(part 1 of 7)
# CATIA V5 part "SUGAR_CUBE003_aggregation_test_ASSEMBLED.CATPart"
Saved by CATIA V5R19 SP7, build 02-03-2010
Part number: sugar_cube_powercopy_revised
Bounding box of the stored display mesh (mm): x -8667.428 to 41555.613, y -8007.522 to 25321.48, z -5486.4 to 45720
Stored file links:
  C:\Users\kmdaub-admin\Desktop\zip\SUGAR_CUBE003_aggregation_test_ASSEMBLED.CATPart
  C:\Users\kmdaub-admin\Desktop\sugar_cubes\sugar_cube_lantern.CATPart
  C:\Users\kmdaub-admin\Desktop\sugar_cubes\sugar-cube-revised\SUGAR_CUBE003.CATPart
  C:\Users\kmdaub-admin\Desktop\sugar_cubes\sugar-cube-revised\sugar_cube003_revised_aggregation_test.xls
  C:\Users\kmdaub-admin\Desktop\zip\sugar_cube003_revised_aggregation_test2.xls
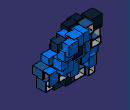
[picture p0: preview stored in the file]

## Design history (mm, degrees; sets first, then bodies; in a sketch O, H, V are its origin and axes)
Parameters
  thickness = 609.6 mm
  grid_spacing = 9144 mm
  overall_height = 39624 mm
  random_clamp = 0.5
AxisSystem1: origin (0, 0, 0), X (1, 0, 0), Y (0, 1, 0), Z (0, 0, 1)
Set1 "framework"
  Point1: (14630.4, 14630.4, 14630.4), in AxisSystem1
Set2 "framework_setup"
  Plane1: type Offset, RefPlane XY plane of AxisSystem1, Offset 39624 {= overall_height}
  Sketch1 on XY plane of AxisSystem1, origin (0, 0, 0), H (1, 0, 0), V (0, 1, 0)
    line L1 (83.4959, 142.8705) -> (139.9184, 442.4027)
    line L2 (383.0281, 86.448) -> (83.4959, 142.8705)
    construction line L3 (383.0281, 86.448) -> (139.9184, 442.4027)
    point P4 (261.4732, 264.4253)
    length L2 = 304.8
    length L1 = 304.8
    perpendicularity: L2 L1
    midpoint: P4 L3
  Sketch2 on Plane1, origin (0, 0, 39624), H (1, 0, 0), V (0, 1, 0)
    line L1 (171.3017, 531.5737) -> (279.4378, 246.6007)
    line L2 (279.4378, 246.6007) -> (564.4108, 354.7368)
    construction line L3 (171.3017, 531.5737) -> (564.4108, 354.7368)
    point P4 (367.8563, 443.1553)
    length L2 = 304.8
    length L1 = 304.8
    perpendicularity: L2 L1
    midpoint: P4 L3
  RectPattern1: of sketch element, direction 1 instances 5, spacing 9144 {= grid_spacing}, along sketch element reversed, direction 2 instances 5, spacing 9144 {= grid_spacing}, along sketch element
  RectPattern2: of sketch element, direction 1 instances 5, spacing 9144 {= grid_spacing}, along sketch element, direction 2 instances 5, spacing 9144 {= grid_spacing}, along sketch element reversed
Set3 "framework_powercopies"
  Set4 "framework_powercopy"
    Line1: type PtPt, FirstPoint vertex of RectPattern1, SecondPoint vertex of RectPattern2
    Point2: type OnCurve, Support Line1, Ratio 0.2
    Point3: type OnCurve, Support Line1, RefPoint Point2, Ratio 0.25 {= 1 / 4}
    Point4: type OnCurve, Support Line1, RefPoint Point2, Ratio 0.5 {= 2 / 4}
    Point5: type OnCurve, Support Line1, RefPoint Point2, Ratio 0.75 {= 3 / 4}
  Set5 "framework_powercopy"
    Line2: type PtPt, FirstPoint vertex of RectPattern1, SecondPoint vertex of RectPattern2
    Point6: type OnCurve, Support Line2, Ratio 0.2
    Point7: type OnCurve, Support Line2, RefPoint Point6, Ratio 0.25 {= 1 / 4}
    Point8: type OnCurve, Support Line2, RefPoint Point6, Ratio 0.5 {= 2 / 4}
    Point9: type OnCurve, Support Line2, RefPoint Point6, Ratio 0.75 {= 3 / 4}
  Set6 "framework_powercopy"
    Line3: type PtPt, FirstPoint vertex of RectPattern1, SecondPoint vertex of RectPattern2
    Point10: type OnCurve, Support Line3, Ratio 0.2
    Point11: type OnCurve, Support Line3, RefPoint Point10, Ratio 0.25 {= 1 / 4}
    Point12: type OnCurve, Support Line3, RefPoint Point10, Ratio 0.5 {= 2 / 4}
    Point13: type OnCurve, Support Line3, RefPoint Point10, Ratio 0.75 {= 3 / 4}
  Set7 "framework_powercopy"
    Line4: type PtPt, FirstPoint vertex of RectPattern1, SecondPoint vertex of RectPattern2
    Point14: type OnCurve, Support Line4, Ratio 0.2
    Point15: type OnCurve, Support Line4, RefPoint Point14, Ratio 0.25 {= 1 / 4}
    Point16: type OnCurve, Support Line4, RefPoint Point14, Ratio 0.5 {= 2 / 4}
    Point17: type OnCurve, Support Line4, RefPoint Point14, Ratio 0.75 {= 3 / 4}
  Set8 "framework_powercopy"
    Line5: type PtPt, FirstPoint vertex of RectPattern1, SecondPoint vertex of RectPattern2
    Point18: type OnCurve, Support Line5, Ratio 0.2
    Point19: type OnCurve, Support Line5, RefPoint Point18, Ratio 0.25 {= 1 / 4}
    Point20: type OnCurve, Support Line5, RefPoint Point18, Ratio 0.5 {= 2 / 4}
    Point21: type OnCurve, Support Line5, RefPoint Point18, Ratio 0.75 {= 3 / 4}
  Set9 "framework_powercopy"
    Line6: type PtPt, FirstPoint vertex of RectPattern1, SecondPoint vertex of RectPattern2
    Point22: type OnCurve, Support Line6, Ratio 0.2
    Point23: type OnCurve, Support Line6, RefPoint Point22, Ratio 0.25 {= 1 / 4}
    Point24: type OnCurve, Support Line6, RefPoint Point22, Ratio 0.5 {= 2 / 4}
    Point25: type OnCurve, Support Line6, RefPoint Point22, Ratio 0.75 {= 3 / 4}
  Set10 "framework_powercopy"
    Line7: type PtPt, FirstPoint vertex of RectPattern1, SecondPoint vertex of RectPattern2
    Point26: type OnCurve, Support Line7, Ratio 0.2
    Point27: type OnCurve, Support Line7, RefPoint Point26, Ratio 0.25 {= 1 / 4}
    Point28: type OnCurve, Support Line7, RefPoint Point26, Ratio 0.5 {= 2 / 4}
    Point29: type OnCurve, Support Line7, RefPoint Point26, Ratio 0.75 {= 3 / 4}
  Set11 "framework_powercopy"
    Line8: type PtPt, FirstPoint vertex of RectPattern1, SecondPoint vertex of RectPattern2
    Point30: type OnCurve, Support Line8, Ratio 0.2
    Point31: type OnCurve, Support Line8, RefPoint Point30, Ratio 0.25 {= 1 / 4}
    Point32: type OnCurve, Support Line8, RefPoint Point30, Ratio 0.5 {= 2 / 4}
    Point33: type OnCurve, Support Line8, RefPoint Point30, Ratio 0.75 {= 3 / 4}
  Set12 "framework_powercopy"
    Line9: type PtPt, FirstPoint vertex of RectPattern1, SecondPoint vertex of RectPattern2
    Point34: type OnCurve, Support Line9, Ratio 0.2
    Point35: type OnCurve, Support Line9, RefPoint Point34, Ratio 0.25 {= 1 / 4}
    Point36: type OnCurve, Support Line9, RefPoint Point34, Ratio 0.5 {= 2 / 4}
    Point37: type OnCurve, Support Line9, RefPoint Point34, Ratio 0.75 {= 3 / 4}
  Set13 "framework_powercopy"
    Line10: type PtPt, FirstPoint vertex of RectPattern1, SecondPoint vertex of RectPattern2
    Point38: type OnCurve, Support Line10, Ratio 0.2
    Point39: type OnCurve, Support Line10, RefPoint Point38, Ratio 0.25 {= 1 / 4}
    Point40: type OnCurve, Support Line10, RefPoint Point38, Ratio 0.5 {= 2 / 4}
    Point41: type OnCurve, Support Line10, RefPoint Point38, Ratio 0.75 {= 3 / 4}
  Set14 "framework_powercopy"
    Line11: type PtPt, FirstPoint vertex of RectPattern1, SecondPoint vertex of RectPattern2
    Point42: type OnCurve, Support Line11, Ratio 0.2
    Point43: type OnCurve, Support Line11, RefPoint Point42, Ratio 0.25 {= 1 / 4}
    Point44: type OnCurve, Support Line11, RefPoint Point42, Ratio 0.5 {= 2 / 4}
    Point45: type OnCurve, Support Line11, RefPoint Point42, Ratio 0.75 {= 3 / 4}
  Set15 "framework_powercopy"
    Line12: type PtPt, FirstPoint vertex of RectPattern1, SecondPoint vertex of RectPattern2
    Point46: type OnCurve, Support Line12, Ratio 0.2
    Point47: type OnCurve, Support Line12, RefPoint Point46, Ratio 0.25 {= 1 / 4}
    Point48: type OnCurve, Support Line12, RefPoint Point46, Ratio 0.5 {= 2 / 4}
    Point49: type OnCurve, Support Line12, RefPoint Point46, Ratio 0.75 {= 3 / 4}
  Set16 "framework_powercopy"
    Line13: type PtPt, FirstPoint vertex of RectPattern1, SecondPoint vertex of RectPattern2
    Point50: type OnCurve, Support Line13, Ratio 0.2
    Point51: type OnCurve, Support Line13, RefPoint Point50, Ratio 0.25 {= 1 / 4}
    Point52: type OnCurve, Support Line13, RefPoint Point50, Ratio 0.5 {= 2 / 4}
    Point53: type OnCurve, Support Line13, RefPoint Point50, Ratio 0.75 {= 3 / 4}
  Set17 "framework_powercopy"
    Line14: type PtPt, FirstPoint vertex of RectPattern1, SecondPoint vertex of RectPattern2
    Point54: type OnCurve, Support Line14, Ratio 0.2
    Point55: type OnCurve, Support Line14, RefPoint Point54, Ratio 0.25 {= 1 / 4}
    Point56: type OnCurve, Support Line14, RefPoint Point54, Ratio 0.5 {= 2 / 4}
    Point57: type OnCurve, Support Line14, RefPoint Point54, Ratio 0.75 {= 3 / 4}
  Set18 "framework_powercopy"
    Line15: type PtPt, FirstPoint vertex of RectPattern1, SecondPoint vertex of RectPattern2
    Point58: type OnCurve, Support Line15, Ratio 0.2
    Point59: type OnCurve, Support Line15, RefPoint Point58, Ratio 0.25 {= 1 / 4}
    Point60: type OnCurve, Support Line15, RefPoint Point58, Ratio 0.5 {= 2 / 4}
    Point61: type OnCurve, Support Line15, RefPoint Point58, Ratio 0.75 {= 3 / 4}
  Set19 "framework_powercopy"
    Line16: type PtPt, FirstPoint vertex of RectPattern1, SecondPoint vertex of RectPattern2
    Point62: type OnCurve, Support Line16, Ratio 0.2
    Point63: type OnCurve, Support Line16, RefPoint Point62, Ratio 0.25 {= 1 / 4}
    Point64: type OnCurve, Support Line16, RefPoint Point62, Ratio 0.5 {= 2 / 4}
    Point65: type OnCurve, Support Line16, RefPoint Point62, Ratio 0.75 {= 3 / 4}
  Set20 "framework_powercopy"
    Line17: type PtPt, FirstPoint vertex of RectPattern1, SecondPoint vertex of RectPattern2
    Point66: type OnCurve, Support Line17, Ratio 0.2
    Point67: type OnCurve, Support Line17, RefPoint Point66, Ratio 0.25 {= 1 / 4}
    Point68: type OnCurve, Support Line17, RefPoint Point66, Ratio 0.5 {= 2 / 4}
    Point69: type OnCurve, Support Line17, RefPoint Point66, Ratio 0.75 {= 3 / 4}
  Set21 "framework_powercopy"
    Line18: type PtPt, FirstPoint vertex of RectPattern1, SecondPoint vertex of RectPattern2
    Point70: type OnCurve, Support Line18, Ratio 0.2
    Point71: type OnCurve, Support Line18, RefPoint Point70, Ratio 0.25 {= 1 / 4}
    Point72: type OnCurve, Support Line18, RefPoint Point70, Ratio 0.5 {= 2 / 4}
    Point73: type OnCurve, Support Line18, RefPoint Point70, Ratio 0.75 {= 3 / 4}
  Set22 "framework_powercopy"
    Line19: type PtPt, FirstPoint vertex of RectPattern1, SecondPoint vertex of RectPattern2
    Point74: type OnCurve, Support Line19, Ratio 0.2
    Point75: type OnCurve, Support Line19, RefPoint Point74, Ratio 0.25 {= 1 / 4}
    Point76: type OnCurve, Support Line19, RefPoint Point74, Ratio 0.5 {= 2 / 4}
    Point77: type OnCurve, Support Line19, RefPoint Point74, Ratio 0.75 {= 3 / 4}
  Set23 "framework_powercopy"
    Line20: type PtPt, FirstPoint vertex of RectPattern1, SecondPoint vertex of RectPattern2
    Point78: type OnCurve, Support Line20, Ratio 0.2
    Point79: type OnCurve, Support Line20, RefPoint Point78, Ratio 0.25 {= 1 / 4}
    Point80: type OnCurve, Support Line20, RefPoint Point78, Ratio 0.5 {= 2 / 4}
    Point81: type OnCurve, Support Line20, RefPoint Point78, Ratio 0.75 {= 3 / 4}
  Set24 "framework_powercopy"
    Line21: type PtPt, FirstPoint vertex of RectPattern1, SecondPoint vertex of RectPattern2
    Point82: type OnCurve, Support Line21, Ratio 0.2
    Point83: type OnCurve, Support Line21, RefPoint Point82, Ratio 0.25 {= 1 / 4}
    Point84: type OnCurve, Support Line21, RefPoint Point82, Ratio 0.5 {= 2 / 4}
    Point85: type OnCurve, Support Line21, RefPoint Point82, Ratio 0.75 {= 3 / 4}
  Set25 "framework_powercopy"
    Line22: type PtPt, FirstPoint vertex of RectPattern1, SecondPoint vertex of RectPattern2
    Point86: type OnCurve, Support Line22, Ratio 0.2
    Point87: type OnCurve, Support Line22, RefPoint Point86, Ratio 0.25 {= 1 / 4}
    Point88: type OnCurve, Support Line22, RefPoint Point86, Ratio 0.5 {= 2 / 4}
    Point89: type OnCurve, Support Line22, RefPoint Point86, Ratio 0.75 {= 3 / 4}
  Set26 "framework_powercopy"
    Line23: type PtPt, FirstPoint vertex of RectPattern1, SecondPoint vertex of RectPattern2
    Point90: type OnCurve, Support Line23, Ratio 0.2
    Point91: type OnCurve, Support Line23, RefPoint Point90, Ratio 0.25 {= 1 / 4}
    Point92: type OnCurve, Support Line23, RefPoint Point90, Ratio 0.5 {= 2 / 4}
    Point93: type OnCurve, Support Line23, RefPoint Point90, Ratio 0.75 {= 3 / 4}
  Set27 "framework_powercopy"
    Line24: type PtPt, FirstPoint vertex of RectPattern1, SecondPoint vertex of RectPattern2
    Point94: type OnCurve, Support Line24, Ratio 0.2
    Point95: type OnCurve, Support Line24, RefPoint Point94, Ratio 0.25 {= 1 / 4}
    Point96: type OnCurve, Support Line24, RefPoint Point94, Ratio 0.5 {= 2 / 4}
    Point97: type OnCurve, Support Line24, RefPoint Point94, Ratio 0.75 {= 3 / 4}
  Line25: type PtPt, FirstPoint sketch element, SecondPoint sketch element
  Point98: type OnCurve, Support Line25, Ratio 0.2
  Point99: type OnCurve, Support Line25, RefPoint Point98, Ratio 0.25 {= 1 / 4}
  Point100: type OnCurve, Support Line25, RefPoint Point98, Ratio 0.5 {= 2 / 4}
  Point101: type OnCurve, Support Line25, RefPoint Point98, Ratio 0.75 {= 3 / 4}
Body1 "powercopy" (main body)
  Point102: (3048 {= Body1.X1}, 0, 0), relative to Point1, in AxisSystem1
  Point103: (-4572 {= Body1.X2}, 0, 0), relative to Point1, in AxisSystem1
  Point104: (0, 3657.6 {= Body1.Y1}, 0), relative to Point1, in AxisSystem1
  Point105: (0, -3657.6 {= Body1.Y2}, 0), relative to Point1, in AxisSystem1
  Plane2: type 3Points, Element1 Point1, Element2 Point104, Element3 Point102
  Plane3: type Offset, RefPlane Plane2, Offset 4267.2 {= Body1.Z1}, reversed
  Plane4: type Offset, RefPlane Plane2, Offset -3048 {= Body1.Z2}, reversed
  Sketch3 on Plane2, origin (0, 0, 14630.4), H (1, 0, 0), V (0, -1, 0)
    reference projected point E1 (17678.4, -14630.4) from Point102
    reference projected point E2 (14630.4, -10972.8) from Point105
    reference projected point E3 (10058.4, -14630.4) from Point103
    reference projected point E4 (14630.4, -18288) from Point104
    line L1 (17678.4, -18288) -> (10058.4, -18288)
    line L2 (10058.4, -18288) -> (10058.4, -10972.8)
    line L3 (10058.4, -10972.8) -> (17678.4, -10972.8)
    line L4 (17678.4, -10972.8) -> (17678.4, -18288)
    coincidence: E4 L1, E3 L2, E2 L3, L4 E1
    perpendicularity: L1 L2, L3 L2
    parallelism: L1 L3, L4 L2
    vertical: L2 V
  Pad1 "cube": profile Sketch3, direction (0, 0, -1), up to Plane3, opposite side up to Plane4
  Plane5: type Offset, RefPlane Plane3, Offset 609.6 {= thickness}
  Plane6: type Offset, RefPlane Plane4, Offset 609.6 {= thickness}, reversed
  Sketch4 on Plane2, origin (0, 0, 14630.4), H (1, 0, 0), V (0, -1, 0)
    reference projected point E1 (17678.4, -14630.4) from Point102
    reference projected point E2 (14630.4, -10972.8) from Point105
    reference projected point E3 (10058.4, -14630.4) from Point103
    reference projected point E4 (14630.4, -18288) from Point104
    construction line L1 (17678.4, -10972.8) -> (10058.4, -10972.8)
    construction line L2 (10058.4, -10972.8) -> (10058.4, -18288)
    construction line L3 (10058.4, -18288) -> (17678.4, -18288)
    construction line L4 (17678.4, -18288) -> (17678.4, -10972.8)
    line L5 (10668, -11582.4) -> (17068.8, -11582.4)
    line L6 (17068.8, -11582.4) -> (17068.8, -17678.4)
    line L7 (17068.8, -17678.4) -> (10668, -17678.4)
    line L8 (10668, -17678.4) -> (10668, -11582.4)
    distance L7 L3 = 609.6 {= thickness}
    distance L8 L2 = 609.6 {= thickness}
    distance L5 L1 = 609.6 {= thickness}
    distance L4 L6 = 609.6 {= thickness}
    horizontal: L1 H, L3 H, L5 H, L7 H
    vertical: L2 V, L4 V, L6 V, L8 V
    coincidence: L4 E1, E3 L2, L3 E4, E2 L1
  Pocket1 "internal_pocket": profile Sketch4, direction (0, 0, 1), up to Plane5, opposite side up to Plane6
  Plane7: type Offset, RefPlane face of Pad1 from Sketch3.L4, Offset 609.6 {= thickness}
  Sketch5 on face of Pad1 from Sketch3.L4, origin (17678.4, 0, 0), H (0, -1, 0), V (0, 0, 1)
    construction line L1 (-10972.8, 18897.6) -> (-18288, 18897.6)
    construction line L2 (-18288, 18897.6) -> (-18288, 11582.4)
    construction line L3 (-18288, 11582.4) -> (-10972.8, 11582.4)
    construction line L4 (-10972.8, 11582.4) -> (-10972.8, 18897.6)
    line L5 (-11582.4, 18288) -> (-17678.4, 18288)
    line L6 (-17678.4, 18288) -> (-17678.4, 12192)
    line L7 (-17678.4, 12192) -> (-11582.4, 12192)
    line L8 (-11582.4, 12192) -> (-11582.4, 18288)
    distance L5 L1 = 609.6 {= thickness}
    distance L6 L2 = 609.6 {= thickness}
    distance L3 L7 = 609.6 {= thickness}
    distance L4 L8 = 609.6 {= thickness}
    horizontal: L1 H, L3 H, L5 H, L7 H
    vertical: L2 V, L4 V, L6 V, L8 V
  Pocket2 "X1_pocket": profile Sketch5, direction (1, 0, 0), up to Plane7, deactivated
  Plane8: type Offset, RefPlane face of Pad1 from Sketch3.L1, Offset 609.6 {= thickness}
  Sketch6 on face of Pad1 from Sketch3.L1, origin (0, 18288, 0), H (1, 0, 0), V (0, 0, 1)
    construction line L1 (17678.4, 18897.6) -> (10058.4, 18897.6)
    construction line L2 (10058.4, 18897.6) -> (10058.4, 11582.4)
    construction line L3 (10058.4, 11582.4) -> (17678.4, 11582.4)
    construction line L4 (17678.4, 11582.4) -> (17678.4, 18897.6)
    line L5 (17068.8, 18288) -> (10668, 18288)
    line L6 (10668, 18288) -> (10668, 12192)
    line L7 (10668, 12192) -> (17068.8, 12192)
    line L8 (17068.8, 12192) -> (17068.8, 18288)
    distance L6 L2 = 609.6 {= thickness}
    distance L4 L8 = 609.6 {= thickness}
    distance L3 L7 = 609.6 {= thickness}
    distance L5 L1 = 609.6 {= thickness}
    horizontal: L1 H, L3 H, L5 H, L7 H
    vertical: L2 V, L4 V, L6 V, L8 V
  Pocket3 "Y1_pocket": profile Sketch6, direction (0, 1, 0), up to Plane8, deactivated
  Plane9: type Offset, RefPlane face of Pad1 from Sketch3.L2, Offset 609.6 {= thickness}
  Sketch7 on face of Pad1 from Sketch3.L2, origin (10058.4, 0, 0), H (0, -1, 0), V (0, 0, 1)
    construction line L1 (-18288, 18897.6) -> (-10972.8, 18897.6)
    construction line L2 (-10972.8, 18897.6) -> (-10972.8, 11582.4)
    construction line L3 (-10972.8, 11582.4) -> (-18288, 11582.4)
    construction line L4 (-18288, 11582.4) -> (-18288, 18897.6)
    line L5 (-17678.4, 18288) -> (-11582.4, 18288)
    line L6 (-11582.4, 18288) -> (-11582.4, 12192)
    line L7 (-11582.4, 12192) -> (-17678.4, 12192)
    line L8 (-17678.4, 12192) -> (-17678.4, 18288)
    distance L5 L1 = 609.6 {= thickness}
    distance L3 L7 = 609.6 {= thickness}
    distance L6 L2 = 609.6 {= thickness}
    distance L4 L8 = 609.6 {= thickness}
    horizontal: L1 H, L3 H, L5 H, L7 H
    vertical: L2 V, L4 V, L6 V, L8 V
  Pocket4 "X2_pocket": profile Sketch7, direction (1, 0, 0), up to Plane9, deactivated
  Plane10: type Offset, RefPlane face of Pad1 from Sketch3.L3, Offset 609.6 {= thickness}
  Sketch8 on face of Pad1 from Sketch3.L3, origin (0, 10972.8, 0), H (-1, 0, 0), V (0, 0, 1)
    construction line L1 (-10058.4, 18897.6) -> (-17678.4, 18897.6)
    construction line L2 (-17678.4, 18897.6) -> (-17678.4, 11582.4)
    construction line L3 (-17678.4, 11582.4) -> (-10058.4, 11582.4)
    construction line L4 (-10058.4, 11582.4) -> (-10058.4, 18897.6)
    line L5 (-10668, 18288) -> (-17068.8, 18288)
    line L6 (-17068.8, 18288) -> (-17068.8, 12192)
    line L7 (-17068.8, 12192) -> (-10668, 12192)
    line L8 (-10668, 12192) -> (-10668, 18288)
    distance L5 L1 = 609.6 {= thickness}
    distance L7 L3 = 609.6 {= thickness}
    distance L6 L2 = 609.6 {= thickness}
    distance L4 L8 = 609.6 {= thickness}
    horizontal: L1 H, L3 H, L5 H, L7 H
    vertical: L2 V, L4 V, L6 V, L8 V
  Pocket5 "Y2_pocket": profile Sketch8, direction (0, -1, 0), up to Plane10
  Translate1: ToTransfor Pocket5, Direction edge [XY plane of AxisSystem1 | ZX plane of AxisSystem1], Length 38.1
Body2 "sugar_cube003_Aa001"
  Line26: type PtDir, RefPoint vertex of RectPattern1, Direction edge [XY plane of AxisSystem1 | ZX plane of AxisSystem1], Start 0, End 4572 {= Body2.X1}
  Line27: type PtDir, RefPoint vertex of RectPattern1, Direction edge [XY plane of AxisSystem1 | ZX plane of AxisSystem1], Start 0, End 3048 {= Body2.X2}
  Line28: type PtDir, RefPoint vertex of RectPattern1, Direction edge [YZ plane of AxisSystem1 | XY plane of AxisSystem1], Start 0, End 5486.4 {= Body2.Y1}
  Line29: type PtDir, RefPoint vertex of RectPattern1, Direction edge [YZ plane of AxisSystem1 | XY plane of AxisSystem1], Start 0, End 3048 {= Body2.Y2}
  Line30: type PtDir, RefPoint vertex of RectPattern1, Direction edge [ZX plane of AxisSystem1 | YZ plane of AxisSystem1], Start 0, End 3962.4 {= Body2.Z1}
  Line31: type PtDir, RefPoint vertex of RectPattern1, Direction edge [ZX plane of AxisSystem1 | YZ plane of AxisSystem1], Start 0, End 4572 {= Body2.Z2}
  Plane11: type Normal, Curve Line26, RefPoint vertex of Line26
  Plane12: type Normal, Curve Line27, RefPoint vertex of Line27
  Plane13: type Normal, Curve Line28, RefPoint vertex of Line28
  Plane14: type Normal, Curve Line29, RefPoint vertex of Line29
  Plane15: type Normal, Curve Line30, RefPoint vertex of Line30
  Plane16: type Normal, Curve Line31, RefPoint vertex of Line31
  Plane17: type 3Points, Element1 vertex of RectPattern1, Element2 vertex of Line28, Element3 vertex of Line26
  Intersect1: ToIntersect1 Plane13, ToIntersect2 Plane12
  Intersect2: ToIntersect1 Plane11, ToIntersect2 Plane13
  Intersect3: ToIntersect1 Plane11, ToIntersect2 Plane14
  Intersect4: ToIntersect1 Plane14, ToIntersect2 Plane12
  MultiSel1
  LineCorner1: Elements ({intersect ToIntersect1 Plane17, ToIntersect2 Intersect3}; {intersect ToIntersect1 Plane17, ToIntersect2 Intersect4}; {intersect ToIntersect1 Plane17, ToIntersect2 Intersect1}; {intersect ToIntersect1 Plane17, ToIntersect2 Intersect2})
  Pad2: profile LineCorner1, up to Plane15, opposite side up to Plane16, deactivated
  Plane18: type Offset, RefPlane Plane14, Offset 609.6 {= thickness}
  Plane19: type Offset, RefPlane Plane13, Offset 609.6 {= thickness}, reversed
  Plane20: type Offset, RefPlane Plane11, Offset 609.6 {= thickness}, reversed
  Plane21: type Offset, RefPlane Plane12, Offset 609.6 {= thickness}
  Plane22: type Offset, RefPlane Plane16, Offset 609.6 {= thickness}
  Plane23: type Offset, RefPlane Plane15, Offset 609.6 {= thickness}, reversed
  Intersect5: ToIntersect1 Plane18, ToIntersect2 Plane11
  Intersect6: ToIntersect1 Plane19, ToIntersect2 Plane11
  Intersect7: ToIntersect1 Plane22, ToIntersect2 Plane11
  Intersect8: ToIntersect1 Plane23, ToIntersect2 Plane11
  Trim1: Trimmed (Intersect5; Intersect8)
  Trim2: Trimmed (Trim1; Intersect6)
  Trim3: Trimmed (Trim2; Intersect7)
  Pocket6: profile Trim3, up to Plane21, deactivated
  Pad3: profile LineCorner1, up to Plane15, opposite side up to Plane16, deactivated
  Intersect9: ToIntersect1 Plane19, ToIntersect2 Plane12
  Intersect10: ToIntersect1 Plane12, ToIntersect2 Plane18
  Intersect11: ToIntersect1 Plane22, ToIntersect2 Plane12
  Intersect12: ToIntersect1 Plane23, ToIntersect2 Plane12
  Trim4: Trimmed (Intersect12; Intersect9)
  Trim5: Trimmed (Trim4; Intersect11)
  Trim6: Trimmed (Trim5; Intersect10)
  Pocket7: profile Trim6, up to Plane20, deactivated
  Intersect13: ToIntersect1 Plane21, ToIntersect2 Plane14
  Intersect14: ToIntersect1 Plane22, ToIntersect2 Plane14
  Intersect15: ToIntersect1 Plane14, ToIntersect2 Plane20
  Intersect16: ToIntersect1 Plane23, ToIntersect2 Plane14
  Trim7: Trimmed (Intersect13; Intersect16)
  Trim8: Trimmed (Trim7; Intersect15)
  Trim9: Trimmed (Trim8; Intersect14)
  Pad4: profile LineCorner1, up to Plane15, opposite side up to Plane16, deactivated
  Pocket8: profile Trim9, up to Plane19, deactivated
  Intersect17: ToIntersect1 Plane20, ToIntersect2 Plane13
  Intersect18: ToIntersect1 Plane22, ToIntersect2 Plane13
  Intersect19: ToIntersect1 Plane21, ToIntersect2 Plane13
  Intersect20: ToIntersect1 Plane23, ToIntersect2 Plane13
  Trim10: Trimmed (Intersect17; Intersect20)
  Trim11: Trimmed (Trim10; Intersect19)
  Trim12: Trimmed (Trim11; Intersect18)
  Pad5: profile LineCorner1, up to Plane15, opposite side up to Plane16, deactivated
  Pocket9: profile Trim12, up to Plane18, deactivated
Body3 "sugar_cube003_Ab001"
  Line32: type PtDir, RefPoint vertex of RectPattern1, Direction edge [XY plane of AxisSystem1 | ZX plane of AxisSystem1], Start 0, End 5181.6 {= Body3.X1}
  Line33: type PtDir, RefPoint vertex of RectPattern1, Direction edge [XY plane of AxisSystem1 | ZX plane of AxisSystem1], Start 0, End 3352.8 {= Body3.X2}
  Line34: type PtDir, RefPoint vertex of RectPattern1, Direction edge [YZ plane of AxisSystem1 | XY plane of AxisSystem1], Start 0, End 5486.4 {= Body3.Y1}
  Line35: type PtDir, RefPoint vertex of RectPattern1, Direction edge [YZ plane of AxisSystem1 | XY plane of AxisSystem1], Start 0, End 4876.8 {= Body3.Y2}
  Line36: type PtDir, RefPoint vertex of RectPattern1, Direction edge [ZX plane of AxisSystem1 | YZ plane of AxisSystem1], Start 0, End 4572 {= Body3.Z1}
  Line37: type PtDir, RefPoint vertex of RectPattern1, Direction edge [ZX plane of AxisSystem1 | YZ plane of AxisSystem1], Start 0, End 3352.8 {= Body3.Z2}
  Plane24: type Normal, Curve Line32, RefPoint vertex of Line32
  Plane25: type Normal, Curve Line33, RefPoint vertex of Line33
  Plane26: type Normal, Curve Line34, RefPoint vertex of Line34
  Plane27: type Normal, Curve Line35, RefPoint vertex of Line35
  Plane28: type Normal, Curve Line36, RefPoint vertex of Line36
  Plane29: type Normal, Curve Line37, RefPoint vertex of Line37
  Plane30: type 3Points, Element1 vertex of RectPattern1, Element2 vertex of Line34, Element3 vertex of Line32
  Intersect21: ToIntersect1 Plane26, ToIntersect2 Plane25
  Intersect22: ToIntersect1 Plane24, ToIntersect2 Plane26
  Intersect23: ToIntersect1 Plane24, ToIntersect2 Plane27
  Intersect24: ToIntersect1 Plane27, ToIntersect2 Plane25
  MultiSel2
  LineCorner2: Elements ({intersect ToIntersect1 Plane30, ToIntersect2 Intersect23}; {intersect ToIntersect1 Plane30, ToIntersect2 Intersect24}; {intersect ToIntersect1 Plane30, ToIntersect2 Intersect21}; {intersect ToIntersect1 Plane30, ToIntersect2 Intersect22})
  Pad6: profile LineCorner2, up to Plane28, opposite side up to Plane29, deactivated
  Plane31: type Offset, RefPlane Plane27, Offset 609.6 {= thickness}
  Plane32: type Offset, RefPlane Plane26, Offset 609.6 {= thickness}, reversed
  Plane33: type Offset, RefPlane Plane24, Offset 609.6 {= thickness}, reversed
  Plane34: type Offset, RefPlane Plane25, Offset 609.6 {= thickness}
  Plane35: type Offset, RefPlane Plane29, Offset 609.6 {= thickness}
  Plane36: type Offset, RefPlane Plane28, Offset 609.6 {= thickness}, reversed
  Intersect25: ToIntersect1 Plane31, ToIntersect2 Plane24
  Intersect26: ToIntersect1 Plane32, ToIntersect2 Plane24
  Intersect27: ToIntersect1 Plane35, ToIntersect2 Plane24
  Intersect28: ToIntersect1 Plane36, ToIntersect2 Plane24
  Trim13: Trimmed (Intersect25; Intersect28)
  Trim14: Trimmed (Trim13; Intersect26)
  Trim15: Trimmed (Trim14; Intersect27)
  Pocket10: profile Trim15, up to Plane34, deactivated
  Pad7: profile LineCorner2, up to Plane28, opposite side up to Plane29, deactivated
  Intersect29: ToIntersect1 Plane32, ToIntersect2 Plane25
  Intersect30: ToIntersect1 Plane25, ToIntersect2 Plane31
  Intersect31: ToIntersect1 Plane35, ToIntersect2 Plane25
  Intersect32: ToIntersect1 Plane36, ToIntersect2 Plane25
  Trim16: Trimmed (Intersect32; Intersect29)
  Trim17: Trimmed (Trim16; Intersect31)
  Trim18: Trimmed (Trim17; Intersect30)
  Pocket11: profile Trim18, up to Plane33, deactivated
  Intersect33: ToIntersect1 Plane34, ToIntersect2 Plane27
  Intersect34: ToIntersect1 Plane35, ToIntersect2 Plane27
  Intersect35: ToIntersect1 Plane27, ToIntersect2 Plane33
  Intersect36: ToIntersect1 Plane36, ToIntersect2 Plane27
  Trim19: Trimmed (Intersect33; Intersect36)
  Trim20: Trimmed (Trim19; Intersect35)
  Trim21: Trimmed (Trim20; Intersect34)
  Pad8: profile LineCorner2, up to Plane28, opposite side up to Plane29, deactivated
  Pocket12: profile Trim21, up to Plane32, deactivated
  Intersect37: ToIntersect1 Plane33, ToIntersect2 Plane26
  Intersect38: ToIntersect1 Plane35, ToIntersect2 Plane26
  Intersect39: ToIntersect1 Plane34, ToIntersect2 Plane26
  Intersect40: ToIntersect1 Plane36, ToIntersect2 Plane26
  Trim22: Trimmed (Intersect37; Intersect40)
  Trim23: Trimmed (Trim22; Intersect39)
  Trim24: Trimmed (Trim23; Intersect38)
  Pad9: profile LineCorner2, up to Plane28, opposite side up to Plane29, deactivated
  Pocket13: profile Trim24, up to Plane31, deactivated
Body4 "sugar_cube003_Ac001"
  Line38: type PtDir, RefPoint vertex of RectPattern1, Direction edge [XY plane of AxisSystem1 | ZX plane of AxisSystem1], Start 0, End 4876.8 {= Body4.X1}
  Line39: type PtDir, RefPoint vertex of RectPattern1, Direction edge [XY plane of AxisSystem1 | ZX plane of AxisSystem1], Start 0, End 5486.4 {= Body4.X2}
  Line40: type PtDir, RefPoint vertex of RectPattern1, Direction edge [YZ plane of AxisSystem1 | XY plane of AxisSystem1], Start 0, End 6096 {= Body4.Y1}
  Line41: type PtDir, RefPoint vertex of RectPattern1, Direction edge [YZ plane of AxisSystem1 | XY plane of AxisSystem1], Start 0, End 5486.4 {= Body4.Y2}
  Line42: type PtDir, RefPoint vertex of RectPattern1, Direction edge [ZX plane of AxisSystem1 | YZ plane of AxisSystem1], Start 0, End 3352.8 {= Body4.Z1}
  Line43: type PtDir, RefPoint vertex of RectPattern1, Direction edge [ZX plane of AxisSystem1 | YZ plane of AxisSystem1], Start 0, End 4572 {= Body4.Z2}
  Plane37: type Normal, Curve Line38, RefPoint vertex of Line38
  Plane38: type Normal, Curve Line39, RefPoint vertex of Line39
  Plane39: type Normal, Curve Line40, RefPoint vertex of Line40
  Plane40: type Normal, Curve Line41, RefPoint vertex of Line41
  Plane41: type Normal, Curve Line42, RefPoint vertex of Line42
  Plane42: type Normal, Curve Line43, RefPoint vertex of Line43
  Plane43: type 3Points, Element1 vertex of RectPattern1, Element2 vertex of Line40, Element3 vertex of Line38
  Intersect41: ToIntersect1 Plane39, ToIntersect2 Plane38
  Intersect42: ToIntersect1 Plane37, ToIntersect2 Plane39
  Intersect43: ToIntersect1 Plane37, ToIntersect2 Plane40
  Intersect44: ToIntersect1 Plane40, ToIntersect2 Plane38
  MultiSel3
  LineCorner3: Elements ({intersect ToIntersect1 Plane43, ToIntersect2 Intersect43}; {intersect ToIntersect1 Plane43, ToIntersect2 Intersect44}; {intersect ToIntersect1 Plane43, ToIntersect2 Intersect41}; {intersect ToIntersect1 Plane43, ToIntersect2 Intersect42})
  Pad10: profile LineCorner3, up to Plane41, opposite side up to Plane42, deactivated
  Plane44: type Offset, RefPlane Plane40, Offset 609.6 {= thickness}
  Plane45: type Offset, RefPlane Plane39, Offset 609.6 {= thickness}, reversed
  Plane46: type Offset, RefPlane Plane37, Offset 609.6 {= thickness}, reversed
  Plane47: type Offset, RefPlane Plane38, Offset 609.6 {= thickness}
  Plane48: type Offset, RefPlane Plane42, Offset 609.6 {= thickness}
  Plane49: type Offset, RefPlane Plane41, Offset 609.6 {= thickness}, reversed
  Intersect45: ToIntersect1 Plane44, ToIntersect2 Plane37
  Intersect46: ToIntersect1 Plane45, ToIntersect2 Plane37
  Intersect47: ToIntersect1 Plane48, ToIntersect2 Plane37
  Intersect48: ToIntersect1 Plane49, ToIntersect2 Plane37
  Trim25: Trimmed (Intersect45; Intersect48)
  Trim26: Trimmed (Trim25; Intersect46)
  Trim27: Trimmed (Trim26; Intersect47)
  Pocket14: profile Trim27, up to Plane47, deactivated
  Pad11: profile LineCorner3, up to Plane41, opposite side up to Plane42, deactivated
  Intersect49: ToIntersect1 Plane45, ToIntersect2 Plane38
  Intersect50: ToIntersect1 Plane38, ToIntersect2 Plane44
  Intersect51: ToIntersect1 Plane48, ToIntersect2 Plane38
  Intersect52: ToIntersect1 Plane49, ToIntersect2 Plane38
  Trim28: Trimmed (Intersect52; Intersect49)
  Trim29: Trimmed (Trim28; Intersect51)
  Trim30: Trimmed (Trim29; Intersect50)
  Pocket15: profile Trim30, up to Plane46, deactivated
  Intersect53: ToIntersect1 Plane47, ToIntersect2 Plane40
  Intersect54: ToIntersect1 Plane48, ToIntersect2 Plane40
  Intersect55: ToIntersect1 Plane40, ToIntersect2 Plane46
  Intersect56: ToIntersect1 Plane49, ToIntersect2 Plane40
  Trim31: Trimmed (Intersect53; Intersect56)
  Trim32: Trimmed (Trim31; Intersect55)
  Trim33: Trimmed (Trim32; Intersect54)
  Pad12: profile LineCorner3, up to Plane41, opposite side up to Plane42, deactivated
  Pocket16: profile Trim33, up to Plane45, deactivated
  Intersect57: ToIntersect1 Plane46, ToIntersect2 Plane39
  Intersect58: ToIntersect1 Plane48, ToIntersect2 Plane39
  Intersect59: ToIntersect1 Plane47, ToIntersect2 Plane39
  Intersect60: ToIntersect1 Plane49, ToIntersect2 Plane39
  Trim34: Trimmed (Intersect57; Intersect60)
  Trim35: Trimmed (Trim34; Intersect59)
  Trim36: Trimmed (Trim35; Intersect58)
  Pad13: profile LineCorner3, up to Plane41, opposite side up to Plane42, deactivated
  Pocket17: profile Trim36, up to Plane44, deactivated
Body5 "sugar_cube003_Ad001"
  Line44: type PtDir, RefPoint vertex of RectPattern1, Direction edge [XY plane of AxisSystem1 | ZX plane of AxisSystem1], Start 0, End 3657.6 {= Body5.X1}
  Line45: type PtDir, RefPoint vertex of RectPattern1, Direction edge [XY plane of AxisSystem1 | ZX plane of AxisSystem1], Start 0, End 3962.4 {= Body5.X2}
  Line46: type PtDir, RefPoint vertex of RectPattern1, Direction edge [YZ plane of AxisSystem1 | XY plane of AxisSystem1], Start 0, End 6096 {= Body5.Y1}
  Line47: type PtDir, RefPoint vertex of RectPattern1, Direction edge [YZ plane of AxisSystem1 | XY plane of AxisSystem1], Start 0, End 4267.2 {= Body5.Y2}
  Line48: type PtDir, RefPoint vertex of RectPattern1, Direction edge [ZX plane of AxisSystem1 | YZ plane of AxisSystem1], Start 0, End 5791.2 {= Body5.Z1}
  Line49: type PtDir, RefPoint vertex of RectPattern1, Direction edge [ZX plane of AxisSystem1 | YZ plane of AxisSystem1], Start 0, End 3352.8 {= Body5.Z2}
  Plane50: type Normal, Curve Line44, RefPoint vertex of Line44
  Plane51: type Normal, Curve Line45, RefPoint vertex of Line45
  Plane52: type Normal, Curve Line46, RefPoint vertex of Line46
  Plane53: type Normal, Curve Line47, RefPoint vertex of Line47
  Plane54: type Normal, Curve Line48, RefPoint vertex of Line48
  Plane55: type Normal, Curve Line49, RefPoint vertex of Line49
  Plane56: type 3Points, Element1 vertex of RectPattern1, Element2 vertex of Line46, Element3 vertex of Line44
  Intersect61: ToIntersect1 Plane52, ToIntersect2 Plane51
  Intersect62: ToIntersect1 Plane50, ToIntersect2 Plane52
  Intersect63: ToIntersect1 Plane50, ToIntersect2 Plane53
  Intersect64: ToIntersect1 Plane53, ToIntersect2 Plane51
  MultiSel4
  LineCorner4: Elements ({intersect ToIntersect1 Plane56, ToIntersect2 Intersect63}; {intersect ToIntersect1 Plane56, ToIntersect2 Intersect64}; {intersect ToIntersect1 Plane56, ToIntersect2 Intersect61}; {intersect ToIntersect1 Plane56, ToIntersect2 Intersect62})
  Pad14: profile LineCorner4, up to Plane54, opposite side up to Plane55
  Plane57: type Offset, RefPlane Plane53, Offset 609.6 {= thickness}
  Plane58: type Offset, RefPlane Plane52, Offset 609.6 {= thickness}, reversed
  Plane59: type Offset, RefPlane Plane50, Offset 609.6 {= thickness}, reversed
  Plane60: type Offset, RefPlane Plane51, Offset 609.6 {= thickness}
  Plane61: type Offset, RefPlane Plane55, Offset 609.6 {= thickness}
  Plane62: type Offset, RefPlane Plane54, Offset 609.6 {= thickness}, reversed
  Intersect65: ToIntersect1 Plane57, ToIntersect2 Plane50
  Intersect66: ToIntersect1 Plane58, ToIntersect2 Plane50
  Intersect67: ToIntersect1 Plane61, ToIntersect2 Plane50
  Intersect68: ToIntersect1 Plane62, ToIntersect2 Plane50
  Trim37: Trimmed (Intersect65; Intersect68)
  Trim38: Trimmed (Trim37; Intersect66)
  Trim39: Trimmed (Trim38; Intersect67)
  Pocket18: profile Trim39, up to Plane60, deactivated
  Pad15: profile LineCorner4, up to Plane54, opposite side up to Plane55, deactivated
  Intersect69: ToIntersect1 Plane58, ToIntersect2 Plane51
  Intersect70: ToIntersect1 Plane51, ToIntersect2 Plane57
  Intersect71: ToIntersect1 Plane61, ToIntersect2 Plane51
  Intersect72: ToIntersect1 Plane62, ToIntersect2 Plane51
  Trim40: Trimmed (Intersect72; Intersect69)
  Trim41: Trimmed (Trim40; Intersect71)
  Trim42: Trimmed (Trim41; Intersect70)
  Pocket19: profile Trim42, up to Plane59, deactivated
  Intersect73: ToIntersect1 Plane60, ToIntersect2 Plane53
  Intersect74: ToIntersect1 Plane61, ToIntersect2 Plane53
  Intersect75: ToIntersect1 Plane53, ToIntersect2 Plane59
  Intersect76: ToIntersect1 Plane62, ToIntersect2 Plane53
  Trim43: Trimmed (Intersect73; Intersect76)
  Trim44: Trimmed (Trim43; Intersect75)
  Trim45: Trimmed (Trim44; Intersect74)
  Pad16: profile LineCorner4, up to Plane54, opposite side up to Plane55, deactivated
  Pocket20: profile Trim45, up to Plane58, deactivated
  Intersect77: ToIntersect1 Plane59, ToIntersect2 Plane52
  Intersect78: ToIntersect1 Plane61, ToIntersect2 Plane52
  Intersect79: ToIntersect1 Plane60, ToIntersect2 Plane52
  Intersect80: ToIntersect1 Plane62, ToIntersect2 Plane52
  Trim46: Trimmed (Intersect77; Intersect80)
  Trim47: Trimmed (Trim46; Intersect79)
  Trim48: Trimmed (Trim47; Intersect78)
  Pad17: profile LineCorner4, up to Plane54, opposite side up to Plane55
  Pocket21: profile Trim48, up to Plane57
Body6 "sugar_cube003_Ae001"
  Line50: type PtDir, RefPoint sketch element, Direction edge [XY plane of AxisSystem1 | ZX plane of AxisSystem1], Start 0, End 6096 {= Body6.X1}
  Line51: type PtDir, RefPoint sketch element, Direction edge [XY plane of AxisSystem1 | ZX plane of AxisSystem1], Start 0, End 3657.6 {= Body6.X2}
  Line52: type PtDir, RefPoint sketch element, Direction edge [YZ plane of AxisSystem1 | XY plane of AxisSystem1], Start 0, End 4267.2 {= Body6.Y1}
  Line53: type PtDir, RefPoint sketch element, Direction edge [YZ plane of AxisSystem1 | XY plane of AxisSystem1], Start 0, End 4876.8 {= Body6.Y2}
  Line54: type PtDir, RefPoint sketch element, Direction edge [ZX plane of AxisSystem1 | YZ plane of AxisSystem1], Start 0, End 4267.2 {= Body6.Z1}
  Line55: type PtDir, RefPoint sketch element, Direction edge [ZX plane of AxisSystem1 | YZ plane of AxisSystem1], Start 0, End 3352.8 {= Body6.Z2}
  Plane63: type Normal, Curve Line50, RefPoint vertex of Line50
  Plane64: type Normal, Curve Line51, RefPoint vertex of Line51
  Plane65: type Normal, Curve Line52, RefPoint vertex of Line52
  Plane66: type Normal, Curve Line53, RefPoint vertex of Line53
  Plane67: type Normal, Curve Line54, RefPoint vertex of Line54
  Plane68: type Normal, Curve Line55, RefPoint vertex of Line55
  Plane69: type 3Points, Element1 sketch element, Element2 vertex of Line52, Element3 vertex of Line50
  Intersect81: ToIntersect1 Plane65, ToIntersect2 Plane64
  Intersect82: ToIntersect1 Plane63, ToIntersect2 Plane65
  Intersect83: ToIntersect1 Plane63, ToIntersect2 Plane66
  Intersect84: ToIntersect1 Plane66, ToIntersect2 Plane64
  MultiSel5
  LineCorner5: Elements ({intersect ToIntersect1 Plane69, ToIntersect2 Intersect83}; {intersect ToIntersect1 Plane69, ToIntersect2 Intersect84}; {intersect ToIntersect1 Plane69, ToIntersect2 Intersect81}; {intersect ToIntersect1 Plane69, ToIntersect2 Intersect82})
  Pad18: profile LineCorner5, up to Plane67, opposite side up to Plane68, deactivated
  Plane70: type Offset, RefPlane Plane66, Offset 609.6 {= thickness}
  Plane71: type Offset, RefPlane Plane65, Offset 609.6 {= thickness}, reversed
  Plane72: type Offset, RefPlane Plane63, Offset 609.6 {= thickness}, reversed
  Plane73: type Offset, RefPlane Plane64, Offset 609.6 {= thickness}
  Plane74: type Offset, RefPlane Plane68, Offset 609.6 {= thickness}
  Plane75: type Offset, RefPlane Plane67, Offset 609.6 {= thickness}, reversed
  Intersect85: ToIntersect1 Plane70, ToIntersect2 Plane63
  Intersect86: ToIntersect1 Plane71, ToIntersect2 Plane63
  Intersect87: ToIntersect1 Plane74, ToIntersect2 Plane63
  Intersect88: ToIntersect1 Plane75, ToIntersect2 Plane63
  Trim49: Trimmed (Intersect85; Intersect88)
  Trim50: Trimmed (Trim49; Intersect86)
  Trim51: Trimmed (Trim50; Intersect87)
  Pocket22: profile Trim51, up to Plane73, deactivated
  Pad19: profile LineCorner5, up to Plane67, opposite side up to Plane68, deactivated
  Intersect89: ToIntersect1 Plane71, ToIntersect2 Plane64
  Intersect90: ToIntersect1 Plane64, ToIntersect2 Plane70
  Intersect91: ToIntersect1 Plane74, ToIntersect2 Plane64
  Intersect92: ToIntersect1 Plane75, ToIntersect2 Plane64
  Trim52: Trimmed (Intersect92; Intersect89)
  Trim53: Trimmed (Trim52; Intersect91)
  Trim54: Trimmed (Trim53; Intersect90)
  Pocket23: profile Trim54, up to Plane72, deactivated
  Intersect93: ToIntersect1 Plane73, ToIntersect2 Plane66
  Intersect94: ToIntersect1 Plane74, ToIntersect2 Plane66
  Intersect95: ToIntersect1 Plane66, ToIntersect2 Plane72
  Intersect96: ToIntersect1 Plane75, ToIntersect2 Plane66
  Trim55: Trimmed (Intersect93; Intersect96)
  Trim56: Trimmed (Trim55; Intersect95)
  Trim57: Trimmed (Trim56; Intersect94)
  Pad20: profile LineCorner5, up to Plane67, opposite side up to Plane68, deactivated
  Pocket24: profile Trim57, up to Plane71, deactivated
  Intersect97: ToIntersect1 Plane72, ToIntersect2 Plane65
  Intersect98: ToIntersect1 Plane74, ToIntersect2 Plane65
  Intersect99: ToIntersect1 Plane73, ToIntersect2 Plane65
  Intersect100: ToIntersect1 Plane75, ToIntersect2 Plane65
  Trim58: Trimmed (Intersect97; Intersect100)
  Trim59: Trimmed (Trim58; Intersect99)
  Trim60: Trimmed (Trim59; Intersect98)
  Pad21: profile LineCorner5, up to Plane67, opposite side up to Plane68, deactivated
  Pocket25: profile Trim60, up to Plane70, deactivated
Body7 "sugar_cube003_Aa002"
  Line56: type PtDir, RefPoint Point14, Direction edge [XY plane of AxisSystem1 | ZX plane of AxisSystem1], Start 0, End 4267.2 {= Body7.X1}
  Line57: type PtDir, RefPoint Point14, Direction edge [XY plane of AxisSystem1 | ZX plane of AxisSystem1], Start 0, End 3962.4 {= Body7.X2}
  Line58: type PtDir, RefPoint Point14, Direction edge [YZ plane of AxisSystem1 | XY plane of AxisSystem1], Start 0, End 6096 {= Body7.Y1}
  Line59: type PtDir, RefPoint Point14, Direction edge [YZ plane of AxisSystem1 | XY plane of AxisSystem1], Start 0, End 5486.4 {= Body7.Y2}
  Line60: type PtDir, RefPoint Point14, Direction edge [ZX plane of AxisSystem1 | YZ plane of AxisSystem1], Start 0, End 4267.2 {= Body7.Z1}
  Line61: type PtDir, RefPoint Point14, Direction edge [ZX plane of AxisSystem1 | YZ plane of AxisSystem1], Start 0, End 3352.8 {= Body7.Z2}
  Plane76: type Normal, Curve Line56, RefPoint vertex of Line56
  Plane77: type Normal, Curve Line57, RefPoint vertex of Line57
  Plane78: type Normal, Curve Line58, RefPoint vertex of Line58
  Plane79: type Normal, Curve Line59, RefPoint vertex of Line59
  Plane80: type Normal, Curve Line60, RefPoint vertex of Line60
  Plane81: type Normal, Curve Line61, RefPoint vertex of Line61
  Plane82: type 3Points, Element1 Point14, Element2 vertex of Line58, Element3 vertex of Line56
  Intersect101: ToIntersect1 Plane78, ToIntersect2 Plane77
  Intersect102: ToIntersect1 Plane76, ToIntersect2 Plane78
  Intersect103: ToIntersect1 Plane76, ToIntersect2 Plane79
  Intersect104: ToIntersect1 Plane79, ToIntersect2 Plane77
  MultiSel6
  LineCorner6: Elements ({intersect ToIntersect1 Plane82, ToIntersect2 Intersect103}; {intersect ToIntersect1 Plane82, ToIntersect2 Intersect104}; {intersect ToIntersect1 Plane82, ToIntersect2 Intersect101}; {intersect ToIntersect1 Plane82, ToIntersect2 Intersect102})
  Pad22: profile LineCorner6, up to Plane80, opposite side up to Plane81
  Plane83: type Offset, RefPlane Plane79, Offset 609.6 {= thickness}
  Plane84: type Offset, RefPlane Plane78, Offset 609.6 {= thickness}, reversed
  Plane85: type Offset, RefPlane Plane76, Offset 609.6 {= thickness}, reversed
  Plane86: type Offset, RefPlane Plane77, Offset 609.6 {= thickness}
  Plane87: type Offset, RefPlane Plane81, Offset 609.6 {= thickness}
  Plane88: type Offset, RefPlane Plane80, Offset 609.6 {= thickness}, reversed
  Intersect105: ToIntersect1 Plane83, ToIntersect2 Plane76
  Intersect106: ToIntersect1 Plane84, ToIntersect2 Plane76
  Intersect107: ToIntersect1 Plane87, ToIntersect2 Plane76
  Intersect108: ToIntersect1 Plane88, ToIntersect2 Plane76
  Trim61: Trimmed (Intersect105; Intersect108)
  Trim62: Trimmed (Trim61; Intersect106)
  Trim63: Trimmed (Trim62; Intersect107)
  Pocket26: profile Trim63, up to Plane86, deactivated
  Pad23: profile LineCorner6, up to Plane80, opposite side up to Plane81, deactivated
  Intersect109: ToIntersect1 Plane84, ToIntersect2 Plane77
  Intersect110: ToIntersect1 Plane77, ToIntersect2 Plane83
  Intersect111: ToIntersect1 Plane87, ToIntersect2 Plane77
  Intersect112: ToIntersect1 Plane88, ToIntersect2 Plane77
  Trim64: Trimmed (Intersect112; Intersect109)
  Trim65: Trimmed (Trim64; Intersect111)
  Trim66: Trimmed (Trim65; Intersect110)
  Pocket27: profile Trim66, up to Plane85, deactivated
  Intersect113: ToIntersect1 Plane86, ToIntersect2 Plane79
  Intersect114: ToIntersect1 Plane87, ToIntersect2 Plane79
  Intersect115: ToIntersect1 Plane79, ToIntersect2 Plane85
  Intersect116: ToIntersect1 Plane88, ToIntersect2 Plane79
  Trim67: Trimmed (Intersect113; Intersect116)
  Trim68: Trimmed (Trim67; Intersect115)
  Trim69: Trimmed (Trim68; Intersect114)
  Pad24: profile LineCorner6, up to Plane80, opposite side up to Plane81, deactivated
  Pocket28: profile Trim69, up to Plane84, deactivated
  Intersect117: ToIntersect1 Plane85, ToIntersect2 Plane78
  Intersect118: ToIntersect1 Plane87, ToIntersect2 Plane78
  Intersect119: ToIntersect1 Plane86, ToIntersect2 Plane78
  Intersect120: ToIntersect1 Plane88, ToIntersect2 Plane78
  Trim70: Trimmed (Intersect117; Intersect120)
  Trim71: Trimmed (Trim70; Intersect119)
  Trim72: Trimmed (Trim71; Intersect118)
  Pad25: profile LineCorner6, up to Plane80, opposite side up to Plane81
  Pocket29: profile Trim72, up to Plane83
